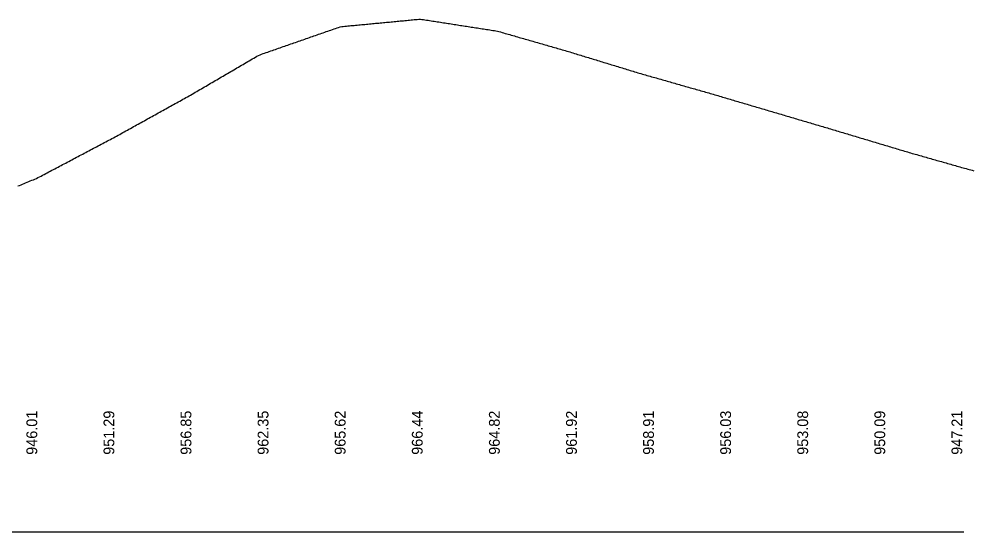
# Model space of a CAD drawing. Extents: x 1573485 to 1576468, y 1104256 to 1106756.
# Drawn here: x 1575843 to 1576463, y 1105506 to 1105839 of the extents above; entities that cross this region are included whole.
import ezdxf

# ---------------------------------------------------------------- set-up
doc = ezdxf.new("R2010")
doc.units = 0
for name, color, linetype in [('RD_DDB_Profile_EX', 7, 'Continuous'), ('RD_DDB_StripGrade', 7, 'Continuous'), ('RD_GPK_Profile_Cell', 7, 'Continuous')]:
    doc.layers.add(name, color=color, linetype=linetype)

msp = doc.modelspace()

# ---------------------------------------------------------------- linework, layer by layer
at = {"layer": 'RD_DDB_Profile_EX'}
for points in [[(1575977.5, 1105802.89), (1575978.5, 1105803.48), (1575979.5, 1105804.06), (1575980.5, 1105804.65), (1575981.5, 1105805.23), (1575982.5, 1105805.82), (1575983.5, 1105806.4), (1575984.5, 1105806.99), (1575985.5, 1105807.57), (1575986.5, 1105808.15), (1575987.5, 1105808.74), (1575988.5, 1105809.32), (1575989.5, 1105809.91), (1575990.5, 1105810.49), (1575991.5, 1105811.08), (1575992.5, 1105811.66), (1575993.5, 1105812.25), (1575994.5, 1105812.83), (1575995.5, 1105813.42), (1575996.5, 1105814), (1575997.5, 1105814.59), (1575998.5, 1105815.17), (1575999.5, 1105815.58), (1576000.5, 1105815.93), (1576001.5, 1105816.28), (1576002.5, 1105816.63), (1576003.5, 1105816.98), (1576004.5, 1105817.33), (1576005.5, 1105817.67), (1576006.5, 1105818.02), (1576007.5, 1105818.37), (1576008.5, 1105818.72), (1576009.5, 1105819.07), (1576010.5, 1105819.42), (1576011.5, 1105819.77), (1576012.5, 1105820.11), (1576013.5, 1105820.46), (1576014.5, 1105820.81), (1576015.5, 1105821.16), (1576016.5, 1105821.51), (1576017.5, 1105821.86), (1576018.5, 1105822.21), (1576019.5, 1105822.55), (1576020.5, 1105822.9), (1576021.5, 1105823.25), (1576022.5, 1105823.6), (1576023.5, 1105823.95), (1576024.5, 1105824.3), (1576025.5, 1105824.64), (1576026.5, 1105824.99), (1576027.5, 1105825.34), (1576028.5, 1105825.69), (1576029.5, 1105826.03), (1576030.5, 1105826.38), (1576031.5, 1105826.73), (1576032.5, 1105827.08), (1576033.5, 1105827.43), (1576034.5, 1105827.77), (1576035.5, 1105828.12), (1576036.5, 1105828.47), (1576037.5, 1105828.82), (1576038.5, 1105829.16), (1576039.5, 1105829.51), (1576040.5, 1105829.86), (1576041.5, 1105830.21), (1576042.5, 1105830.55), (1576043.5, 1105830.9), (1576044.5, 1105831.25), (1576045.5, 1105831.6), (1576046.5, 1105831.94), (1576047.5, 1105832.29), (1576048.5, 1105832.64), (1576049.5, 1105832.99), (1576050.5, 1105833.34), (1576051.5, 1105833.68), (1576052.5, 1105833.86), (1576053.5, 1105833.96), (1576054.5, 1105834.05), (1576055.5, 1105834.15), (1576056.5, 1105834.24), (1576057.5, 1105834.34), (1576058.5, 1105834.43), (1576059.5, 1105834.53), (1576060.5, 1105834.62), (1576061.5, 1105834.71), (1576062.5, 1105834.81), (1576063.5, 1105834.9), (1576064.5, 1105835), (1576065.5, 1105835.09), (1576066.5, 1105835.19), (1576067.5, 1105835.28), (1576068.5, 1105835.38), (1576069.5, 1105835.47), (1576070.5, 1105835.57), (1576071.5, 1105835.66), (1576072.5, 1105835.76), (1576073.5, 1105835.85), (1576074.5, 1105835.95), (1576075.5, 1105836.04), (1576076.5, 1105836.14), (1576077.5, 1105836.23)], [(1576077.5, 1105836.23), (1576078.5, 1105836.33), (1576079.5, 1105836.42), (1576080.5, 1105836.52), (1576081.5, 1105836.61), (1576082.5, 1105836.71), (1576083.5, 1105836.8), (1576084.5, 1105836.9), (1576085.5, 1105836.99), (1576086.5, 1105837.08), (1576087.5, 1105837.18), (1576088.5, 1105837.27), (1576089.5, 1105837.37), (1576090.5, 1105837.46), (1576091.5, 1105837.56), (1576092.5, 1105837.65), (1576093.5, 1105837.75), (1576094.5, 1105837.84), (1576095.5, 1105837.94), (1576096.5, 1105838.03), (1576097.5, 1105838.13), (1576098.5, 1105838.22), (1576099.5, 1105838.32), (1576100.5, 1105838.41), (1576101.5, 1105838.51), (1576102.5, 1105838.6), (1576103.5, 1105838.69), (1576104.5, 1105838.53), (1576105.5, 1105838.38), (1576106.5, 1105838.22), (1576107.5, 1105838.07), (1576108.5, 1105837.91), (1576109.5, 1105837.76), (1576110.5, 1105837.6), (1576111.5, 1105837.44), (1576112.5, 1105837.29), (1576113.5, 1105837.13), (1576114.5, 1105836.98), (1576115.5, 1105836.82), (1576116.5, 1105836.67), (1576117.5, 1105836.51), (1576118.5, 1105836.35), (1576119.5, 1105836.2), (1576120.5, 1105836.04), (1576121.5, 1105835.89), (1576122.5, 1105835.73), (1576123.5, 1105835.58), (1576124.5, 1105835.42), (1576125.5, 1105835.26), (1576126.5, 1105835.11), (1576127.5, 1105834.95), (1576128.5, 1105834.8), (1576129.5, 1105834.64), (1576130.5, 1105834.49), (1576131.5, 1105834.33), (1576132.5, 1105834.17), (1576133.5, 1105834.02), (1576134.5, 1105833.86), (1576135.5, 1105833.71), (1576136.5, 1105833.55), (1576137.5, 1105833.4), (1576138.5, 1105833.24), (1576139.5, 1105833.08), (1576140.5, 1105832.93), (1576141.5, 1105832.77), (1576142.5, 1105832.62), (1576143.5, 1105832.46), (1576144.5, 1105832.31), (1576145.5, 1105832.15), (1576146.5, 1105831.99), (1576147.5, 1105831.84), (1576148.5, 1105831.68), (1576149.5, 1105831.53), (1576150.5, 1105831.37), (1576151.5, 1105831.22), (1576152.5, 1105831.06), (1576153.5, 1105830.89), (1576154.5, 1105830.6), (1576155.5, 1105830.32), (1576156.5, 1105830.03), (1576157.5, 1105829.74), (1576158.5, 1105829.45), (1576159.5, 1105829.17), (1576160.5, 1105828.88), (1576161.5, 1105828.59), (1576162.5, 1105828.3), (1576163.5, 1105828.01), (1576164.5, 1105827.73), (1576165.5, 1105827.44), (1576166.5, 1105827.15), (1576167.5, 1105826.86), (1576168.5, 1105826.58), (1576169.5, 1105826.29), (1576170.5, 1105826), (1576171.5, 1105825.71), (1576172.5, 1105825.43), (1576173.5, 1105825.14), (1576174.5, 1105824.85), (1576175.5, 1105824.56), (1576176.5, 1105824.27), (1576177.5, 1105823.99)], [(1576177.5, 1105823.99), (1576178.5, 1105823.7), (1576179.5, 1105823.41), (1576180.5, 1105823.12), (1576181.5, 1105822.84), (1576182.5, 1105822.55), (1576183.5, 1105822.26), (1576184.5, 1105821.97), (1576185.5, 1105821.68), (1576186.5, 1105821.4), (1576187.5, 1105821.11), (1576188.5, 1105820.82), (1576189.5, 1105820.53), (1576190.5, 1105820.25), (1576191.5, 1105819.96), (1576192.5, 1105819.67), (1576193.5, 1105819.38), (1576194.5, 1105819.1), (1576195.5, 1105818.81), (1576196.5, 1105818.52), (1576197.5, 1105818.24), (1576198.5, 1105817.95), (1576199.5, 1105817.65), (1576200.5, 1105817.35), (1576201.5, 1105817.04), (1576202.5, 1105816.74), (1576203.5, 1105816.43), (1576204.5, 1105816.13), (1576205.5, 1105815.82), (1576206.5, 1105815.52), (1576207.5, 1105815.21), (1576208.5, 1105814.91), (1576209.5, 1105814.6), (1576210.5, 1105814.3), (1576211.5, 1105813.99), (1576212.5, 1105813.69), (1576213.5, 1105813.38), (1576214.5, 1105813.08), (1576215.5, 1105812.77), (1576216.5, 1105812.47), (1576217.5, 1105812.16), (1576218.5, 1105811.86), (1576219.5, 1105811.55), (1576220.5, 1105811.25), (1576221.5, 1105810.94), (1576222.5, 1105810.64), (1576223.5, 1105810.33), (1576224.5, 1105810.03), (1576225.5, 1105809.72), (1576226.5, 1105809.42), (1576227.5, 1105809.11), (1576228.5, 1105808.81), (1576229.5, 1105808.5), (1576230.5, 1105808.2), (1576231.5, 1105807.89), (1576232.5, 1105807.59), (1576233.5, 1105807.28), (1576234.5, 1105806.98), (1576235.5, 1105806.67), (1576236.5, 1105806.37), (1576237.5, 1105806.06), (1576238.5, 1105805.76), (1576239.5, 1105805.45), (1576240.5, 1105805.15), (1576241.5, 1105804.84), (1576242.5, 1105804.52), (1576243.5, 1105804.2), (1576244.5, 1105803.89), (1576245.5, 1105803.61), (1576246.5, 1105803.33), (1576247.5, 1105803.05), (1576248.5, 1105802.76), (1576249.5, 1105802.48), (1576250.5, 1105802.2), (1576251.5, 1105801.91), (1576252.5, 1105801.63), (1576253.5, 1105801.34), (1576254.5, 1105801.06), (1576255.5, 1105800.77), (1576256.5, 1105800.49), (1576257.5, 1105800.2), (1576258.5, 1105799.92), (1576259.5, 1105799.63), (1576260.5, 1105799.34), (1576261.5, 1105799.06), (1576262.5, 1105798.77), (1576263.5, 1105798.49), (1576264.5, 1105798.2), (1576265.5, 1105797.92), (1576266.5, 1105797.63), (1576267.5, 1105797.35), (1576268.5, 1105797.06), (1576269.5, 1105796.78), (1576270.5, 1105796.49), (1576271.5, 1105796.21), (1576272.5, 1105795.92), (1576273.5, 1105795.63), (1576274.5, 1105795.35), (1576275.5, 1105795.06), (1576276.5, 1105794.78), (1576277.5, 1105794.49)], [(1575877.5, 1105747.47), (1575878.5, 1105747.99), (1575879.5, 1105748.52), (1575880.5, 1105749.05), (1575881.5, 1105749.58), (1575882.5, 1105750.11), (1575883.5, 1105750.64), (1575884.5, 1105751.17), (1575885.5, 1105751.69), (1575886.5, 1105752.22), (1575887.5, 1105752.75), (1575888.5, 1105753.28), (1575889.5, 1105753.81), (1575890.5, 1105754.34), (1575891.5, 1105754.87), (1575892.5, 1105755.4), (1575893.5, 1105755.92), (1575894.5, 1105756.45), (1575895.5, 1105756.98), (1575896.5, 1105757.51), (1575897.5, 1105758.04), (1575898.5, 1105758.57), (1575899.5, 1105759.1), (1575900.5, 1105759.63), (1575901.5, 1105760.15), (1575902.5, 1105760.68), (1575903.5, 1105761.21), (1575904.5, 1105761.74), (1575905.5, 1105762.27), (1575906.5, 1105762.82), (1575907.5, 1105763.38), (1575908.5, 1105763.93), (1575909.5, 1105764.49), (1575910.5, 1105765.04), (1575911.5, 1105765.59), (1575912.5, 1105766.15), (1575913.5, 1105766.7), (1575914.5, 1105767.26), (1575915.5, 1105767.81), (1575916.5, 1105768.37), (1575917.5, 1105768.92), (1575918.5, 1105769.48), (1575919.5, 1105770.03), (1575920.5, 1105770.58), (1575921.5, 1105771.14), (1575922.5, 1105771.69), (1575923.5, 1105772.25), (1575924.5, 1105772.8), (1575925.5, 1105773.36), (1575926.5, 1105773.91), (1575927.5, 1105774.47), (1575928.5, 1105775.02), (1575929.5, 1105775.58), (1575930.5, 1105776.13), (1575931.5, 1105776.68), (1575932.5, 1105777.24), (1575933.5, 1105777.79), (1575934.5, 1105778.35), (1575935.5, 1105778.9), (1575936.5, 1105779.46), (1575937.5, 1105780.01), (1575938.5, 1105780.57), (1575939.5, 1105781.12), (1575940.5, 1105781.68), (1575941.5, 1105782.23), (1575942.5, 1105782.79), (1575943.5, 1105783.34), (1575944.5, 1105783.9), (1575945.5, 1105784.45), (1575946.5, 1105785.01), (1575947.5, 1105785.56), (1575948.5, 1105786.12), (1575949.5, 1105786.67), (1575950.5, 1105787.22), (1575951.5, 1105787.78), (1575952.5, 1105788.34), (1575953.5, 1105788.89), (1575954.5, 1105789.45), (1575955.5, 1105790.04), (1575956.5, 1105790.62), (1575957.5, 1105791.2), (1575958.5, 1105791.79), (1575959.5, 1105792.37), (1575960.5, 1105792.96), (1575961.5, 1105793.54), (1575962.5, 1105794.13), (1575963.5, 1105794.71), (1575964.5, 1105795.29), (1575965.5, 1105795.88), (1575966.5, 1105796.46), (1575967.5, 1105797.05), (1575968.5, 1105797.63), (1575969.5, 1105798.22), (1575970.5, 1105798.8), (1575971.5, 1105799.39), (1575972.5, 1105799.97), (1575973.5, 1105800.55), (1575974.5, 1105801.14), (1575975.5, 1105801.72), (1575976.5, 1105802.31), (1575977.5, 1105802.89)], [(1576277.5, 1105794.49), (1576278.5, 1105794.21), (1576279.5, 1105793.92), (1576280.5, 1105793.64), (1576281.5, 1105793.35), (1576282.5, 1105793.07), (1576283.5, 1105792.78), (1576284.5, 1105792.5), (1576285.5, 1105792.21), (1576286.5, 1105791.93), (1576287.5, 1105791.64), (1576288.5, 1105791.35), (1576289.5, 1105791.07), (1576290.5, 1105790.78), (1576291.5, 1105790.5), (1576292.5, 1105790.21), (1576293.5, 1105789.93), (1576294.5, 1105789.63), (1576295.5, 1105789.33), (1576296.5, 1105789.03), (1576297.5, 1105788.73), (1576298.5, 1105788.43), (1576299.5, 1105788.14), (1576300.5, 1105787.84), (1576301.5, 1105787.55), (1576302.5, 1105787.25), (1576303.5, 1105786.96), (1576304.5, 1105786.66), (1576305.5, 1105786.37), (1576306.5, 1105786.07), (1576307.5, 1105785.78), (1576308.5, 1105785.48), (1576309.5, 1105785.19), (1576310.5, 1105784.89), (1576311.5, 1105784.6), (1576312.5, 1105784.3), (1576313.5, 1105784.01), (1576314.5, 1105783.71), (1576315.5, 1105783.42), (1576316.5, 1105783.12), (1576317.5, 1105782.83), (1576318.5, 1105782.53), (1576319.5, 1105782.24), (1576320.5, 1105781.94), (1576321.5, 1105781.64), (1576322.5, 1105781.35), (1576323.5, 1105781.05), (1576324.5, 1105780.76), (1576325.5, 1105780.46), (1576326.5, 1105780.17), (1576327.5, 1105779.87), (1576328.5, 1105779.58), (1576329.5, 1105779.28), (1576330.5, 1105778.99), (1576331.5, 1105778.69), (1576332.5, 1105778.4), (1576333.5, 1105778.1), (1576334.5, 1105777.81), (1576335.5, 1105777.51), (1576336.5, 1105777.22), (1576337.5, 1105776.92), (1576338.5, 1105776.63), (1576339.5, 1105776.33), (1576340.5, 1105776.04), (1576341.5, 1105775.74), (1576342.5, 1105775.45), (1576343.5, 1105775.15), (1576344.5, 1105774.86), (1576345.5, 1105774.56), (1576346.5, 1105774.26), (1576347.5, 1105773.97), (1576348.5, 1105773.67), (1576349.5, 1105773.38), (1576350.5, 1105773.08), (1576351.5, 1105772.79), (1576352.5, 1105772.49), (1576353.5, 1105772.2), (1576354.5, 1105771.9), (1576355.5, 1105771.6), (1576356.5, 1105771.31), (1576357.5, 1105771.01), (1576358.5, 1105770.72), (1576359.5, 1105770.42), (1576360.5, 1105770.13), (1576361.5, 1105769.83), (1576362.5, 1105769.54), (1576363.5, 1105769.24), (1576364.5, 1105768.94), (1576365.5, 1105768.65), (1576366.5, 1105768.35), (1576367.5, 1105768.06), (1576368.5, 1105767.76), (1576369.5, 1105767.46), (1576370.5, 1105767.16), (1576371.5, 1105766.86), (1576372.5, 1105766.56), (1576373.5, 1105766.26), (1576374.5, 1105765.96), (1576375.5, 1105765.66), (1576376.5, 1105765.36), (1576377.5, 1105765.07)], [(1576377.5, 1105765.07), (1576378.5, 1105764.77), (1576379.5, 1105764.47), (1576380.5, 1105764.17), (1576381.5, 1105763.87), (1576382.5, 1105763.57), (1576383.5, 1105763.27), (1576384.5, 1105762.97), (1576385.5, 1105762.67), (1576386.5, 1105762.37), (1576387.5, 1105762.07), (1576388.5, 1105761.78), (1576389.5, 1105761.48), (1576390.5, 1105761.18), (1576391.5, 1105760.88), (1576392.5, 1105760.58), (1576393.5, 1105760.28), (1576394.5, 1105759.98), (1576395.5, 1105759.68), (1576396.5, 1105759.38), (1576397.5, 1105759.08), (1576398.5, 1105758.78), (1576399.5, 1105758.48), (1576400.5, 1105758.19), (1576401.5, 1105757.89), (1576402.5, 1105757.59), (1576403.5, 1105757.29), (1576404.5, 1105756.99), (1576405.5, 1105756.69), (1576406.5, 1105756.39), (1576407.5, 1105756.09), (1576408.5, 1105755.79), (1576409.5, 1105755.49), (1576410.5, 1105755.19), (1576411.5, 1105754.89), (1576412.5, 1105754.6), (1576413.5, 1105754.3), (1576414.5, 1105754), (1576415.5, 1105753.7), (1576416.5, 1105753.4), (1576417.5, 1105753.1), (1576418.5, 1105752.81), (1576419.5, 1105752.51), (1576420.5, 1105752.21), (1576421.5, 1105751.92), (1576422.5, 1105751.62), (1576423.5, 1105751.33), (1576424.5, 1105751.04), (1576425.5, 1105750.76), (1576426.5, 1105750.47), (1576427.5, 1105750.19), (1576428.5, 1105749.91), (1576429.5, 1105749.62), (1576430.5, 1105749.34), (1576431.5, 1105749.06), (1576432.5, 1105748.77), (1576433.5, 1105748.49), (1576434.5, 1105748.21), (1576435.5, 1105747.92), (1576436.5, 1105747.64), (1576437.5, 1105747.36), (1576438.5, 1105747.07), (1576439.5, 1105746.79), (1576440.5, 1105746.51), (1576441.5, 1105746.22), (1576442.5, 1105745.94), (1576443.5, 1105745.66), (1576444.5, 1105745.37), (1576445.5, 1105745.09), (1576446.5, 1105744.81), (1576447.5, 1105744.52), (1576448.5, 1105744.24), (1576449.5, 1105743.96), (1576450.5, 1105743.67), (1576451.5, 1105743.39), (1576452.5, 1105743.11), (1576453.5, 1105742.82), (1576454.5, 1105742.54), (1576455.5, 1105742.26), (1576456.5, 1105741.97), (1576457.5, 1105741.69), (1576458.5, 1105741.41), (1576459.5, 1105741.15), (1576460.5, 1105740.89), (1576461.5, 1105740.63), (1576462.5, 1105740.37), (1576462.53, 1105740.36)], [(1575842.5, 1105730.46), (1575843.5, 1105730.86), (1575844.5, 1105731.27), (1575845.5, 1105731.68), (1575846.5, 1105732.09), (1575847.5, 1105732.49), (1575848.5, 1105732.9), (1575849.5, 1105733.31), (1575850.5, 1105733.72), (1575851.5, 1105734.12), (1575852.5, 1105734.53), (1575853.5, 1105734.95), (1575854.5, 1105735.37), (1575855.5, 1105735.84), (1575856.5, 1105736.37), (1575857.5, 1105736.9), (1575858.5, 1105737.43), (1575859.5, 1105737.95), (1575860.5, 1105738.48), (1575861.5, 1105739.01), (1575862.5, 1105739.54), (1575863.5, 1105740.07), (1575864.5, 1105740.6), (1575865.5, 1105741.12), (1575866.5, 1105741.65), (1575867.5, 1105742.18), (1575868.5, 1105742.71), (1575869.5, 1105743.24), (1575870.5, 1105743.77), (1575871.5, 1105744.29), (1575872.5, 1105744.82), (1575873.5, 1105745.35), (1575874.5, 1105745.88), (1575875.5, 1105746.41), (1575876.5, 1105746.94), (1575877.5, 1105747.47)]]:
    msp.add_lwpolyline(points, dxfattribs=at)
at = {"layer": 'RD_GPK_Profile_Cell'}
msp.add_line((1574956, 1105506.08), (1576456, 1105506.08), dxfattribs=at)

# ---------------------------------------------------------------- texts
at = {"layer": 'RD_DDB_StripGrade'}
for s, p in [('946.01', (1575855, 1105556.08)), ('951.29', (1575905, 1105556.08)), ('956.85', (1575955, 1105556.08)), ('962.35', (1576005, 1105556.08)), ('965.62', (1576055, 1105556.08)), ('966.44', (1576105, 1105556.08)), ('964.82', (1576155, 1105556.08)), ('961.92', (1576205, 1105556.08)), ('958.91', (1576255, 1105556.08)), ('956.03', (1576305, 1105556.08)), ('953.08', (1576355, 1105556.08)), ('950.09', (1576405, 1105556.08)), ('947.21', (1576455, 1105556.08))]:
    msp.add_text(s, height=7, rotation=90, dxfattribs=at).set_placement(p)

doc.saveas('drawing.dxf')
